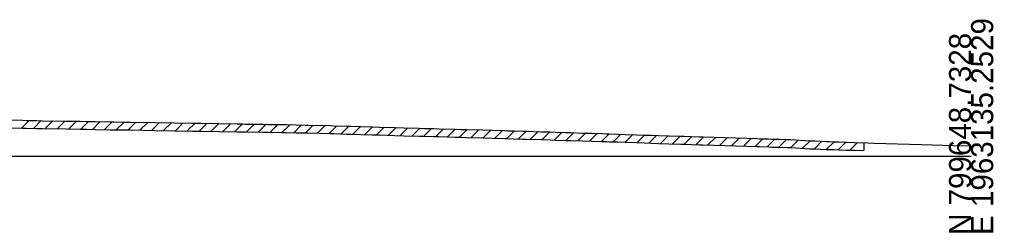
# Model space of a CAD drawing. Extents: x -26 to 1403, y -10 to 19587.
# Drawn here: x 279.4 to 402.8, y 12990.3 to 13017.3 of the extents above; entities that cross this region are included whole.
import ezdxf

# ---------------------------------------------------------------- set-up
doc = ezdxf.new("R2010")
doc.units = 0
for name, color, linetype in [('RD_GPK_XS_Cell', 7, 'Continuous'), ('RD_XS_ExGround', 7, 'Continuous'), ('RD_XS_ExPaveRet', 7, 'Continuous')]:
    doc.layers.add(name, color=color, linetype=linetype)

msp = doc.modelspace()

# ---------------------------------------------------------------- linework, layer by layer
at = {"layer": 'RD_GPK_XS_Cell'}
msp.add_line((200, 13000), (400, 13000), dxfattribs=at)
at = {"layer": 'RD_XS_ExGround'}
msp.add_lwpolyline([(277.84, 13004.57), (279.76, 13004.53), (280.27, 13004.52), (281.57, 13004.5), (282.3, 13004.48), (285.31, 13004.44), (287.07, 13004.4), (287.88, 13004.39), (288.98, 13004.37), (290.88, 13004.34), (291.35, 13004.33), (292.75, 13004.31), (293.46, 13004.3), (296.55, 13004.25), (299.04, 13004.21), (301.31, 13004.17), (302.03, 13004.16), (302.44, 13004.15), (304.67, 13004.12), (306.97, 13004.08), (307.69, 13004.07), (308, 13004.06), (310.23, 13004.03), (310.92, 13004.01), (312.64, 13003.99), (313.25, 13003.98), (314.45, 13003.96), (315.59, 13003.93), (315.98, 13003.92), (318.8, 13003.85), (319.25, 13003.84), (320.83, 13003.79), (321.38, 13003.78), (322.65, 13003.74), (324.13, 13003.7), (325.03, 13003.67), (326.95, 13003.62), (328.1, 13003.58), (330.02, 13003.53), (330.64, 13003.51), (331.95, 13003.47), (332.53, 13003.46), (334.59, 13003.4), (335.37, 13003.38), (336.03, 13003.36), (338.1, 13003.3), (339.31, 13003.26), (340.88, 13003.22), (341.23, 13003.21), (341.99, 13003.19), (343.15, 13003.15), (343.66, 13003.14), (345.57, 13003.08), (346.65, 13003.05), (347.3, 13003.03), (348.59, 13002.99), (349.25, 13002.97), (350.73, 13002.91), (351.92, 13002.89), (353.19, 13002.85), (353.79, 13002.83), (354.14, 13002.81), (355.21, 13002.78), (356.15, 13002.74), (357.62, 13002.7), (358.57, 13002.66), (359.45, 13002.63), (360.39, 13002.6), (361.71, 13002.55), (363.19, 13002.51), (363.62, 13002.5), (364.56, 13002.47), (365.54, 13002.44), (365.98, 13002.42), (367.43, 13002.38), (368.78, 13002.34), (370.14, 13002.3), (371.56, 13002.25), (372.86, 13002.21), (373.2, 13002.2), (374.34, 13002.17), (374.74, 13002.14), (375.69, 13002.13), (376.69, 13002.1), (377.14, 13002.08), (379.57, 13001.93), (380.18, 13001.93), (381.62, 13001.84), (382.07, 13001.83), (382.65, 13001.81), (383.24, 13001.8), (384.19, 13001.76), (385.27, 13001.73), (386.93, 13001.67), (387.69, 13001.65), (393.73, 13001.47), (397.76, 13001.34), (400, 13001.29)], dxfattribs=at)
at = {"layer": 'RD_XS_ExPaveRet'}
for p, q in [((279.65, 13003.53), (280.64, 13004.51)), ((281.15, 13003.51), (282.13, 13004.49)), ((282.65, 13003.48), (283.64, 13004.46)), ((284.15, 13003.45), (285.14, 13004.44)), ((285.65, 13003.43), (286.64, 13004.41)), ((287.15, 13003.4), (288.14, 13004.39)), ((288.65, 13003.38), (289.64, 13004.36)), ((290.15, 13003.35), (291.14, 13004.34)), ((291.65, 13003.33), (292.64, 13004.31)), ((293.15, 13003.3), (294.14, 13004.29)), ((294.65, 13003.28), (295.64, 13004.26)), ((296.15, 13003.26), (297.14, 13004.24)), ((297.65, 13003.23), (298.64, 13004.22)), ((299.15, 13003.21), (300.14, 13004.19)), ((300.65, 13003.18), (301.64, 13004.17)), ((302.15, 13003.16), (303.14, 13004.14)), ((303.65, 13003.13), (304.64, 13004.12)), ((305.15, 13003.11), (306.14, 13004.09)), ((306.65, 13003.08), (307.64, 13004.07)), ((308.15, 13003.06), (309.14, 13004.04)), ((309.65, 13003.03), (310.64, 13004.02)), ((311.15, 13003.01), (312.14, 13003.99)), ((312.65, 13002.99), (313.64, 13003.97)), ((314.15, 13002.96), (315.13, 13003.94)), ((315.65, 13002.93), (316.63, 13003.9)), ((317.15, 13002.89), (318.13, 13003.86)), ((277.84, 13003.57), (279.76, 13003.53)), ((279.76, 13003.53), (280.27, 13003.52)), ((280.27, 13003.52), (281.57, 13003.5)), ((281.57, 13003.5), (282.3, 13003.48)), ((282.3, 13003.48), (285.31, 13003.44)), ((285.31, 13003.44), (287.07, 13003.4)), ((287.07, 13003.4), (287.88, 13003.39)), ((287.88, 13003.39), (288.98, 13003.37)), ((288.98, 13003.37), (290.88, 13003.34)), ((290.88, 13003.34), (291.35, 13003.33)), ((291.35, 13003.33), (292.75, 13003.31)), ((292.75, 13003.31), (293.46, 13003.3)), ((293.46, 13003.3), (296.55, 13003.25)), ((296.55, 13003.25), (299.04, 13003.21)), ((299.04, 13003.21), (301.31, 13003.17)), ((301.31, 13003.17), (302.03, 13003.16)), ((302.03, 13003.16), (302.44, 13003.15)), ((302.44, 13003.15), (304.67, 13003.12)), ((304.67, 13003.12), (306.97, 13003.08)), ((306.97, 13003.08), (307.69, 13003.07)), ((307.69, 13003.07), (308, 13003.06)), ((308, 13003.06), (310.23, 13003.03)), ((310.23, 13003.03), (310.92, 13003.01)), ((310.92, 13003.01), (312.64, 13002.99)), ((312.64, 13002.99), (313.25, 13002.98)), ((313.25, 13002.98), (314.45, 13002.96)), ((314.45, 13002.96), (315.59, 13002.93)), ((315.59, 13002.93), (315.98, 13002.92)), ((315.98, 13002.92), (318.8, 13002.85)), ((318.65, 13002.85), (319.63, 13003.82)), ((318.8, 13002.85), (319.25, 13002.84)), ((319.25, 13002.84), (320.83, 13002.79)), ((320.15, 13002.81), (321.13, 13003.78)), ((320.83, 13002.79), (321.38, 13002.78)), ((321.38, 13002.78), (322.65, 13002.74)), ((321.65, 13002.77), (322.62, 13003.74)), ((322.65, 13002.74), (324.13, 13002.7)), ((323.15, 13002.72), (324.13, 13003.7)), ((324.13, 13002.7), (325.03, 13002.67)), ((324.65, 13002.68), (325.63, 13003.66)), ((325.03, 13002.67), (326.95, 13002.62)), ((326.15, 13002.64), (327.13, 13003.61)), ((326.95, 13002.62), (328.1, 13002.58)), ((327.65, 13002.6), (328.63, 13003.57)), ((329.15, 13002.56), (330.13, 13003.53)), ((330.65, 13002.51), (331.62, 13003.48)), ((332.15, 13002.47), (333.13, 13003.44)), ((333.65, 13002.43), (334.63, 13003.4)), ((335.15, 13002.38), (336.12, 13003.35)), ((336.65, 13002.34), (337.62, 13003.31)), ((338.15, 13002.3), (339.12, 13003.27)), ((339.65, 13002.25), (340.63, 13003.22)), ((341.15, 13002.21), (342.13, 13003.18)), ((342.65, 13002.17), (343.62, 13003.14)), ((344.15, 13002.12), (345.12, 13003.09)), ((345.65, 13002.08), (346.62, 13003.05)), ((347.15, 13002.03), (348.13, 13003)), ((348.65, 13001.99), (349.62, 13002.96)), ((350.15, 13001.94), (351.12, 13002.9)), ((351.65, 13001.89), (352.62, 13002.86)), ((353.15, 13001.85), (354.12, 13002.81)), ((354.65, 13001.8), (355.62, 13002.76)), ((356.15, 13001.74), (357.12, 13002.71)), ((357.65, 13001.69), (358.62, 13002.66)), ((359.15, 13001.64), (360.12, 13002.61)), ((328.1, 13002.58), (330.02, 13002.53)), ((330.02, 13002.53), (330.64, 13002.51)), ((330.64, 13002.51), (331.95, 13002.47)), ((331.95, 13002.47), (332.53, 13002.46)), ((332.53, 13002.46), (334.59, 13002.4)), ((334.59, 13002.4), (335.37, 13002.38)), ((335.37, 13002.38), (336.03, 13002.36)), ((336.03, 13002.36), (338.1, 13002.3)), ((338.1, 13002.3), (339.31, 13002.26)), ((339.31, 13002.26), (340.88, 13002.22)), ((340.88, 13002.22), (341.23, 13002.21)), ((341.23, 13002.21), (341.99, 13002.19)), ((341.99, 13002.19), (343.15, 13002.15)), ((343.15, 13002.15), (343.66, 13002.14)), ((343.66, 13002.14), (345.57, 13002.08)), ((345.57, 13002.08), (346.65, 13002.05)), ((346.65, 13002.05), (347.3, 13002.03)), ((347.3, 13002.03), (348.59, 13001.99)), ((348.59, 13001.99), (349.25, 13001.97)), ((349.25, 13001.97), (350.73, 13001.91)), ((350.73, 13001.91), (351.92, 13001.89)), ((351.92, 13001.89), (353.19, 13001.85)), ((353.19, 13001.85), (353.79, 13001.83)), ((353.79, 13001.83), (354.14, 13001.81)), ((354.14, 13001.81), (355.21, 13001.78)), ((355.21, 13001.78), (356.15, 13001.74)), ((356.15, 13001.74), (357.62, 13001.7)), ((357.62, 13001.7), (358.57, 13001.66)), ((358.57, 13001.66), (359.45, 13001.63)), ((359.45, 13001.63), (360.39, 13001.6)), ((360.39, 13001.6), (361.71, 13001.55)), ((360.65, 13001.59), (361.62, 13002.56)), ((361.71, 13001.55), (363.19, 13001.51)), ((362.15, 13001.54), (363.13, 13002.52)), ((363.19, 13001.51), (363.62, 13001.5)), ((363.62, 13001.5), (364.56, 13001.47)), ((363.65, 13001.5), (364.62, 13002.47)), ((364.56, 13001.47), (365.54, 13001.44)), ((365.15, 13001.45), (366.12, 13002.42)), ((365.54, 13001.44), (365.98, 13001.42)), ((365.98, 13001.42), (367.43, 13001.38)), ((366.65, 13001.4), (367.62, 13002.37)), ((367.43, 13001.38), (368.78, 13001.34)), ((368.15, 13001.36), (369.12, 13002.33)), ((369.65, 13001.31), (370.62, 13002.28)), ((371.15, 13001.26), (372.12, 13002.23)), ((372.65, 13001.22), (373.62, 13002.19)), ((374.15, 13001.17), (375.12, 13002.14)), ((375.65, 13001.13), (376.62, 13002.1)), ((377.15, 13001.08), (378.09, 13002.02)), ((378.65, 13000.99), (379.6, 13001.93)), ((380.15, 13000.93), (381.09, 13001.87)), ((381.65, 13000.84), (382.63, 13001.81)), ((383.15, 13000.8), (384.12, 13001.76)), ((384.65, 13000.75), (385.62, 13001.72)), ((386.42, 13001.69), (386.42, 13000.69)), ((368.78, 13001.34), (370.14, 13001.3)), ((370.14, 13001.3), (371.56, 13001.25)), ((371.56, 13001.25), (372.86, 13001.21)), ((372.86, 13001.21), (373.2, 13001.2)), ((373.2, 13001.2), (374.34, 13001.17)), ((374.34, 13001.17), (374.74, 13001.14)), ((374.74, 13001.14), (375.69, 13001.13)), ((375.69, 13001.13), (376.69, 13001.1)), ((376.69, 13001.1), (377.14, 13001.08)), ((377.14, 13001.08), (379.57, 13000.93)), ((379.57, 13000.93), (380.18, 13000.93)), ((380.18, 13000.93), (381.62, 13000.84)), ((381.62, 13000.84), (382.07, 13000.83)), ((382.07, 13000.83), (382.65, 13000.81)), ((382.65, 13000.81), (383.24, 13000.8)), ((383.24, 13000.8), (384.19, 13000.76)), ((384.19, 13000.76), (385.27, 13000.73)), ((385.27, 13000.73), (386.42, 13000.69))]:
    msp.add_line(p, q, dxfattribs=at)

# ---------------------------------------------------------------- texts
at = {"layer": 'RD_GPK_XS_Cell'}
for s, p in [('E 1963135.2529', (402.8, 12990)), ('N 799648.7328', (400, 12990))]:
    msp.add_text(s, height=2.8, rotation=90, dxfattribs=at).set_placement(p)

doc.saveas('drawing.dxf')
